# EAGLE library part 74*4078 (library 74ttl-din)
8-input OR/NOR, complementary outputs
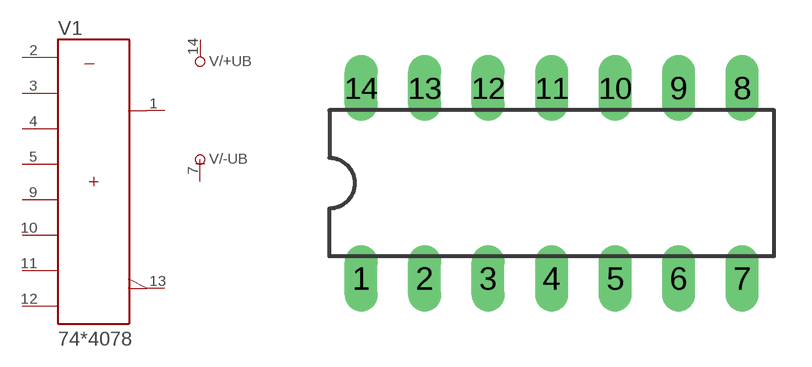
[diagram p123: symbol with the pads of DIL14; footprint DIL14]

Designator prefix V; gates /+UB=+UB /-UB=-UB 1=4078

## 744078N  [DIL14]
1  1:Y  out
2  1:A  in
3  1:B  in
4  1:C  in
5  1:D  in
7  /-UB:-UB  pwr
9  1:E  in
10  1:F  in
11  1:G  in
12  1:H  in
13  1:W  out
14  /+UB:+UB  pwr

## Footprint DIL14 (pad centres in mm)
Dual In Line Package
drill 0.813 long: 1 -7.62,-3.81; 2 -5.08,-3.81; 3 -2.54,-3.81; 4 0,-3.81; 5 2.54,-3.81; 6 5.08,-3.81; 7 7.62,-3.81; 8 7.62,3.81; 9 5.08,3.81; 10 2.54,3.81; 11 0,3.81; 12 -2.54,3.81; 13 -5.08,3.81; 14 -7.62,3.81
